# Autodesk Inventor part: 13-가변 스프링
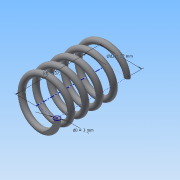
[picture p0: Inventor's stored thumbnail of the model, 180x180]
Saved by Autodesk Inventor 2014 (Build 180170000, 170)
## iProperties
Created: 2015-09
Part Number: 13-가변 스프링
Material: 강철, 탄소
Document SubType Name: Modeling
Designer: study
Density: 1 g/cm^3
Appearance: 반연마
Mass: 2.3997 g
Surface Area: 32.5491 cm^2
Volume: 2.3997 cm^3
Author: study
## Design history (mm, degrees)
sketch "스케치1"
  geometry: L1 (0, 0)-(11, 0); L2 (11, 0)-(11, 36.411); L3 (11, 36.411)-(0, 36.411); L4 (0, 36.411)-(0, 0); C1 r 1.5 at (11, 0)
  constraints: 8 end point, 2 parallel, 1 centre point, 1 coincident, 1 horizontal, 1 perpendicular
  dimensions: "d0" = 3 diameter of C1; "d1" = 36.4112 distance of L3.end L1.start (derived); "d2" = 22 diameter of L2 L4
feature "코일1" sketch "스케치1" pitch "d3" = 10; turns "d5" = 5; dims "d4" = 36.4112 (= d1), "d6" = 0, angle "d7" = 90 deg, angle "d8" = 90 deg, "d9" = 0, "d10" = 0
sketch "스케치2"
  geometry: L1 (-12.5, 0)-(-9.5, 0) reference; 1 further point
  constraints: 1 horizontal alignment
extrude "돌출1" cut sketch "스케치2" stored distance "d11" = 10; taper "d12" = 0 deg
node "작업 평면1"
sketch "스케치3"
  geometry: L1 (-9.5, 0)-(-12.5, 0) reference; 1 further point
  constraints: 1 horizontal alignment
extrude "돌출2" cut sketch "스케치3" stored distance "d14" = 10; taper "d15" = 0 deg
node "솔리드1"
node "절단 모서리 투영1"
node "절단 모서리 투영2"
other parameters: "d13" = 36.4112 (= d1)
